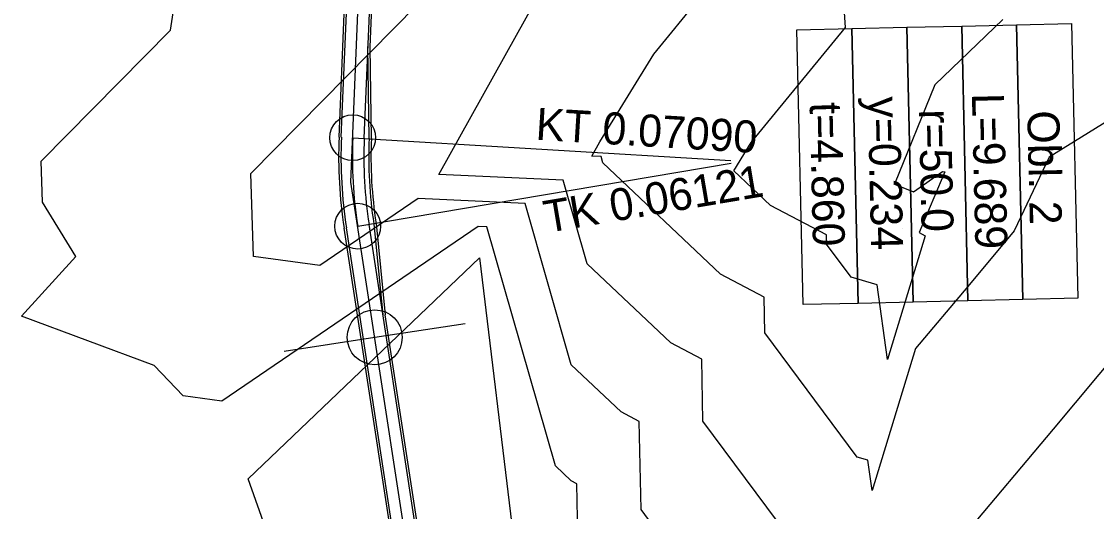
# Model space of a CAD drawing. Extents: x -549394 to -546608, y -1037055 to -1033629.
# Drawn here: x -547932.9 to -547815.5, y -1034572.2 to -1034518.7 of the extents above; entities that cross this region are included whole.
import ezdxf

# ---------------------------------------------------------------- set-up
doc = ezdxf.new("R2010")
doc.units = 0
for name, color, linetype in [('hlavni_vrst', 7, 'Continuous'), ('norm_vrst', 7, 'Continuous'), ('POLYGONY_SITUACE_PO', 7, 'Continuous'), ('u_sirka_1_5m', 7, 'Continuous'), ('x_navrh_C211', 7, 'Continuous'), ('x_osa_C211', 7, 'Continuous'), ('x_popis_oblouky_C211', 7, 'Continuous'), ('x_popis_pricne_rezy_C211', 7, 'Continuous')]:
    doc.layers.add(name, color=color, linetype=linetype)

msp = doc.modelspace()

# ---------------------------------------------------------------- linework, layer by layer
at = {"layer": 'hlavni_vrst'}
for p, q in [((-547863.82, -1034522.3), (-547858.15, -1034515.37)), ((-547869.69, -1034531.9), (-547863.82, -1034522.3)), ((-547811.09, -1034527.65), (-547820.62, -1034533.57)), ((-547870.56, -1034533.46), (-547869.69, -1034531.9)), ((-547869.55, -1034533.5), (-547870.56, -1034533.46)), ((-547869.36, -1034534.18), (-547869.55, -1034533.5)), ((-547856.51, -1034546.33), (-547869.36, -1034534.18)), ((-547820.62, -1034533.57), (-547824.44, -1034541.59)), ((-547824.44, -1034541.59), (-547829.52, -1034547.66)), ((-547851.77, -1034548.83), (-547856.51, -1034546.33)), ((-547829.52, -1034547.66), (-547835.23, -1034554.45)), ((-547851.69, -1034552.72), (-547851.77, -1034548.83)), ((-547841.58, -1034566.29), (-547851.69, -1034552.72)), ((-547835.23, -1034554.45), (-547839.96, -1034569.96)), ((-547840.42, -1034566.64), (-547841.58, -1034566.29)), ((-547839.96, -1034569.96), (-547840.42, -1034566.64))]:
    msp.add_line(p, q, dxfattribs=at)
at = {"layer": 'norm_vrst'}
for p, q in [((-547916.59, -1034519.69), (-547911.7, -1034486.8)), ((-547842.87, -1034519.39), (-547843.38, -1034511.76)), ((-547887.28, -1034535.44), (-547875.58, -1034514.45)), ((-547907.82, -1034535.35), (-547889.61, -1034516.88)), ((-547825.69, -1034518.53), (-547833.1, -1034525.66)), ((-547930.71, -1034534.01), (-547916.59, -1034519.69)), ((-547853.16, -1034531.96), (-547842.87, -1034519.39)), ((-547833.1, -1034525.66), (-547837.5, -1034536.52)), ((-547855.05, -1034535.06), (-547853.16, -1034531.96)), ((-547930.56, -1034538.48), (-547930.71, -1034534.01)), ((-547907.52, -1034544.41), (-547907.82, -1034535.35)), ((-547851.07, -1034538.82), (-547855.05, -1034535.06)), ((-547835.43, -1034537.34), (-547832.26, -1034535.12)), ((-547832.01, -1034535.15), (-547834.81, -1034541.78)), ((-547832.26, -1034535.12), (-547832.01, -1034535.15)), ((-547873.71, -1034536.06), (-547887.28, -1034535.44)), ((-547871.09, -1034545.2), (-547873.71, -1034536.06)), ((-547837.5, -1034536.52), (-547835.43, -1034537.34)), ((-547926.95, -1034544.4), (-547930.56, -1034538.48)), ((-547889.56, -1034538.08), (-547900.27, -1034545.37)), ((-547877.87, -1034538.61), (-547889.56, -1034538.08)), ((-547872.82, -1034556.23), (-547877.87, -1034538.61)), ((-547844.95, -1034542.03), (-547851.07, -1034538.82)), ((-547883, -1034541.13), (-547910.99, -1034560.18)), ((-547882.04, -1034541.17), (-547883, -1034541.13)), ((-547874.54, -1034567.25), (-547882.04, -1034541.17)), ((-547801.2, -1034540.52), (-547820.19, -1034563.23)), ((-547844.93, -1034543.06), (-547844.95, -1034542.03)), ((-547834.16, -1034542.14), (-547838.28, -1034555.65)), ((-547836.61, -1034541.34), (-547836.61, -1034541.34)), ((-547836.61, -1034541.34), (-547836.61, -1034541.34)), ((-547836.61, -1034541.34), (-547836.61, -1034541.34)), ((-547836.61, -1034541.34), (-547836.61, -1034541.34)), ((-547836.61, -1034541.34), (-547836.61, -1034541.34)), ((-547836.61, -1034541.34), (-547836.61, -1034541.34)), ((-547834.81, -1034541.78), (-547834.16, -1034542.14)), ((-547842.26, -1034546.66), (-547844.93, -1034543.06)), ((-547932.87, -1034550.93), (-547926.95, -1034544.4)), ((-547908.1, -1034568.67), (-547882.84, -1034544.56)), ((-547900.27, -1034545.37), (-547907.52, -1034544.41)), ((-547882.84, -1034544.56), (-547879.18, -1034574.92)), ((-547861.95, -1034553.84), (-547871.09, -1034545.2)), ((-547839.41, -1034547.5), (-547842.26, -1034546.66)), ((-547838.28, -1034555.65), (-547839.41, -1034547.5)), ((-547918.39, -1034556.28), (-547932.87, -1034550.93)), ((-547858.58, -1034555.62), (-547861.95, -1034553.84)), ((-547915.22, -1034559.62), (-547918.39, -1034556.28)), ((-547867.39, -1034561.35), (-547872.82, -1034556.23)), ((-547858.44, -1034562.37), (-547858.58, -1034555.62)), ((-547910.99, -1034560.18), (-547915.22, -1034559.62)), ((-547865.39, -1034562.41), (-547867.39, -1034561.35)), ((-547845.65, -1034579.54), (-547858.44, -1034562.37)), ((-547865.2, -1034572.02), (-547865.39, -1034562.41)), ((-547820.19, -1034563.23), (-547833.27, -1034578.79)), ((-547872.84, -1034568.87), (-547874.54, -1034567.25)), ((-547906.03, -1034574.52), (-547908.1, -1034568.67)), ((-547872.21, -1034569.2), (-547872.84, -1034568.87)), ((-547872.08, -1034575.43), (-547872.21, -1034569.2)), ((-547860.31, -1034578.59), (-547865.2, -1034572.02))]:
    msp.add_line(p, q, dxfattribs=at)
at = {"layer": 'POLYGONY_SITUACE_PO'}
for centre in [(-547896.69, -1034531.43), (-547896.15, -1034541.09)]:
    msp.add_circle(centre, 2.5, dxfattribs=at)
at = {"layer": 'u_sirka_1_5m'}
msp.add_circle((-547894.29, -1034553.22), 3, dxfattribs=at)
at = {"layer": 'x_navrh_C211'}
for p, q in [((-547897.94, -1034531.38), (-547896.27, -1034490.94)), ((-547895.44, -1034531.49), (-547893.77, -1034491.05)), ((-547894.91, -1034531.51), (-547895.03, -1034521.49)), ((-547894.66, -1034531.51), (-547894.78, -1034521.5)), ((-547888.31, -1034583.9), (-547894.91, -1034540.9)), ((-547894.39, -1034540.82), (-547893.4, -1034550.78)), ((-547894.14, -1034540.79), (-547893.15, -1034550.75)), ((-547890.78, -1034584.28), (-547897.39, -1034541.28))]:
    msp.add_line(p, q, dxfattribs=at)
for points in [[(-547898.19, -1034531.37), (-547896.52, -1034490.93)], [(-547894.78, -1034521.5), (-547893.52, -1034491.06)], [(-547891.66, -1034580.17), (-547897.63, -1034541.32)], [(-547888.06, -1034583.87), (-547893.15, -1034550.75)]]:
    msp.add_lwpolyline(points, dxfattribs=at)
for radius, start, end in [(51.5, 177.6366, 188.7374), (51.25, 177.6366, 188.7374), (48.75, 177.6366, 188.7374), (48.22, 177.6366, 188.7374), (47.97, 177.6287, 188.7453)]:
    msp.add_arc((-547846.73, -1034533.5), radius, start, end, dxfattribs=at)
at = {"layer": 'x_osa_C211'}
msp.add_lwpolyline([(-547888.19, -1034592.9), (-547896.89, -1034536.29), (-547893.86, -1034463.03)], dxfattribs=at)
msp.add_arc((-547846.73, -1034533.5), 50, 177.6366, 188.7374, dxfattribs=at)
at = {"layer": 'x_popis_oblouky_C211'}
for points in [[(-547842.18, -1034519.52), (-547841.48, -1034549.52), (-547847.48, -1034549.65), (-547848.18, -1034519.66)], [(-547836.18, -1034519.38), (-547835.49, -1034549.38), (-547841.48, -1034549.52), (-547842.18, -1034519.52)], [(-547830.18, -1034519.25), (-547829.49, -1034549.24), (-547835.49, -1034549.38), (-547836.18, -1034519.38)], [(-547824.18, -1034519.11), (-547823.49, -1034549.1), (-547829.49, -1034549.24), (-547830.18, -1034519.25)], [(-547818.19, -1034518.97), (-547817.49, -1034548.96), (-547823.49, -1034549.1), (-547824.18, -1034519.11)]]:
    msp.add_lwpolyline(points, close=True, dxfattribs=at)
for points in [[(-547896.69, -1034531.43), (-547855.39, -1034533.93)], [(-547896.15, -1034541.09), (-547855.35, -1034534.21)]]:
    msp.add_lwpolyline(points, dxfattribs=at)
at = {"layer": 'x_popis_pricne_rezy_C211'}
msp.add_lwpolyline([(-547904.17, -1034554.74), (-547894.29, -1034553.22), (-547884.4, -1034551.7)], dxfattribs=at)

# ---------------------------------------------------------------- texts
at = {"layer": 'x_popis_oblouky_C211'}
for s, rotation, p in [('y=0.234', 271.3479, (-547840.45, -1034526.97)), ('L=9.689', 271.3479, (-547829.07, -1034526.59)), ('KT 0.07090', 356.5403, (-547876.77, -1034531.65)), ('t=4.860', 271.3479, (-547846.79, -1034527.59)), ('r=50.0', 271.3479, (-547834.86, -1034528.36)), ('Obl. 2', 271.3479, (-547823.02, -1034528.49)), ('TK 0.06121', 9.5793, (-547875.51, -1034541.83))]:
    msp.add_text(s, height=3.5, rotation=rotation, dxfattribs=at).set_placement(p)

doc.saveas('drawing.dxf')
